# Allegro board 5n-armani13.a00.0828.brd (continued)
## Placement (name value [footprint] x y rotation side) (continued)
PR9413  4.7Ohm  [TX_R0603_H24]  105.82 101.75 90 bottom
PR9414  0Ohm  [TX_R0603_SHORT]  116.92 103.61 0 bottom
PR9415  10KOhm  [TX_R0402]  117.42 95.56 90 bottom
PR9416  4.7KOhm  [TX_R0402]  108.56 96.76 90 bottom
PR9417  2.2Ohm  [TX_R0805_H26]  116.56 97.16 45 bottom
PR9419  845Ohm  [TX_R0402]  110.11 94.6 270 bottom
PR9420  845Ohm  [TX_R0402]  107.19 92.53 90 bottom
PR9421  0Ohm  [TX_R0402_0OHM]  115.86 107.42 270 bottom
PR9422  887Ohm  [TX_R0402]  108.13 92.53 270 bottom
PR9423  10KOhm  [TX_R0402]  112.73 106.07 270 bottom
PR9424  845Ohm  [TX_R0402]  110.01 92.53 90 bottom
PR9425  1Ohm  [TX_R0402]  107.29 94.54 270 bottom
PR9426  0Ohm  [TX_R0402_0OHM]  115.86 105.77 90 bottom
PR9427  10KOhm  [TX_R0402]  114.92 105.77 270 bottom
PR9428  1Ohm  [TX_R0402]  106.35 94.54 270 bottom
PR9429  845Ohm  [TX_R0402]  111.89 92.53 270 bottom
PR9430  10OHM  [TX_R0402]  113.77 92.53 270 bottom
PR9431  887Ohm  [TX_R0402]  110.95 92.53 270 bottom
PR9432  0Ohm  [TX_R0402_0OHM]  114.5 94.16 90 bottom
PR9433  10KOhm  [TX_R0402]  112.66 94.82 270 bottom
PR9434  0Ohm  [TX_R0402_0OHM]  102.34 98.17 0 bottom
PR9435  41.2KOHM  [TX_R0402]  107.87 98.75 0 bottom
PR9436  10OHM  [TX_R0402]  116.36 94.64 270 bottom
PR9437  0Ohm  [TX_R0402_0OHM]  103.96 98.17 0 bottom
PR9438  14.3KOhm  [TX_R0402]  105.74 98.17 180 bottom
PR9439  0Ohm  [TX_R0402_0OHM]  102.34 97.23 0 bottom
PR9440  69.8KOHM  [TX_R0402]  103.96 97.23 0 bottom
PR9441  2.61KOhm  [TX_R0402]  105.74 97.23 0 bottom
PR9442  61.9KOHM  [TX_R0402]  107.28 97.13 270 bottom
PR9443  1.27KOHM  [TX_R0402]  102.34 96.29 0 bottom
PR9444  31.6KOhm  [TX_R0402]  103.96 96.29 0 bottom
PR9445  16.5KOhm  [TX_R0402]  104.65 99.33 0 bottom
PR9446  9.76KOHM  [TX_R0402]  105.93 99.8 270 bottom
PR9447  590OHM  [TX_R0402]  107.95 99.68 0 bottom
PR9448  3.9Ohm  [TX_R0402]  104.14 101.86 180 bottom
PR9449  0Ohm  [TX_R0402_0OHM]  145.62 83.01 0 bottom
PR9450  0Ohm  [TX_R0402_0OHM]  110.41 106.07 90 bottom
PR9451  0Ohm  [TX_R0402_0OHM]  145.62 80.2 0 bottom
PR9452  0Ohm  [TX_R0402_0OHM]  114.71 92.53 270 bottom
PR9453  0Ohm  [TX_R0402_0OHM]  116.59 92.53 90 bottom
PR9454  60.4KOhm  [TX_R0402]  115.42 94.16 270 bottom
PR9455  0Ohm  [TX_R0402_0OHM]  111.73 94.29 90 bottom
PR9456  0Ohm  [TX_R0402_SHORT]  115.65 108.69 0 bottom
PR9457  12KOhm  [R0402_H14]  107.85 102.64 0 bottom
PR9458  10KOhm  [TX_R0402]  143.97 83.01 180 bottom
PR9459  10KOhm  [TX_R0402]  145.62 81.13 180 bottom
PR9460  10KOhm  [TX_R0402]  145.62 79.25 0 bottom
PR9500  100KOhm  [TX_R0402]  163.88 63.93 45 top
PR9501  2.2Ohm  [TX_R0805_H26]  166.4 69.62 90 bottom
PR9502  10KOhm  [TX_R0402]  167.69 67.08 0 bottom
PR9503  10KOhm  [TX_R0402]  163.2 64.59 45 top
PR9504  20KOhm  [TX_R0402]  167.69 66.14 0 bottom
PR9505  100KOhm  [TX_R0402]  165.07 109.6 90 top
PR9506  2.2Ohm  [TX_R0805_H26]  173.58 113.39 180 top
PR9507  10KOhm  [TX_R0402]  165.51 113.18 270 bottom
PR9508  10KOhm  [TX_R0402]  170.28 111.41 270 top
PR9509  5.9KOHM  [TX_R0402]  167.39 113.18 270 bottom
PR9600  0Ohm  [VX_R0805_SMALL_SHORT]  122.31 101.07 180 bottom
PR9601  0Ohm  [VX_R0805_SMALL_SHORT]  122.31 102.8 180 bottom
PR9602  0Ohm  [VX_R0805_SMALL_SHORT]  122.31 104.52 180 bottom
PR9603  0Ohm  [TX_R0805_0OHM_H26]  130.77 96.65 180 bottom
PR9604  8.2KOhm  [TX_R0402]  128.8 95.18 180 bottom
PR9605  0Ohm  [TX_R0805_0OHM_H26]  133.1 96.12 90 bottom
PR9606  4.7OHM  [TX_R1206_H30]  135.1 101.37 180 top
PR9607  0Ohm  [TX_R0805_0OHM_H26]  118.95 105.01 90 bottom
PR9608  8.2KOhm  [TX_R0402]  119.46 107.34 90 bottom
PR9609  0Ohm  [TX_R0805_0OHM_H26]  127.66 104.93 180 bottom
PR9610  4.7OHM  [TX_R1206_H30]  127.61 108.36 180 top
PR9800  0Ohm  [TX_R0603_SHORT]  198.53 66.96 90 bottom
PR9801  0Ohm  [TX_R0402_0OHM]  191.74 67.72 0 top
PR9802  100KOhm  [TX_R0402]  195.61 64.04 270 bottom
PR9803  100KOhm  [TX_R0402]  192.56 64.01 270 bottom
PR9804  100KOhm  [TX_R0402]  191.29 64.01 270 bottom
PR9805  150KOhm  [TX_R0402]  191.74 65.69 180 top
PR9806  100KOhm  [TX_R0402]  194.59 64.04 90 bottom
PR9807  100KOhm  [TX_R0402]  193.57 64.01 90 bottom
PR9808  100KOhm  [TX_R0402]  190.27 64.04 90 bottom
PR9809  5.1OHM  [TX_R0402]  192.43 70.26 270 top
PR9810  2.21KOhm  [TX_R0402]  192.58 70.39 90 bottom
PR9811  6.8OHM  [TX_R0402]  191.57 70.39 270 bottom
PR9812  20KOhm  [TX_R0402]  193.51 70.39 270 bottom
PR9814  10KOhm  [TX_R0402]  192.35 63.71 90 top
PR9815  0Ohm  [TX_R0402_SHORT]  193.29 63.71 270 top
PRT7800  10KOhm  [TX_R0402_H22]  143.41 57.1 0 bottom
PRT7801  10KOhm  [TX_R0402_H22]  143.87 66.22 180 bottom
PRT7802  10KOhm  [TX_R0402_H22]  143.99 32.82 270 bottom
PRT9400  100KOHM  [TX_R0402_H24]  140.11 97.44 0 bottom
PRT9401  100KOHM  [TX_R0402_H24]  138.42 97.44 180 bottom
PT7700  TPC26T_50  [NB_TPC26T_50]  202.62 22.63 180 bottom
PT7701  TPC26T_50  [NB_TPC26T_50]  197.16 27.74 0 top
PT7702  TPC26T_50  [NB_TPC26T_50]  198.87 27.31 180 bottom
PT8700  TPC28T  [NB_TPC28T_68]  171.86 38.81 0 top
PT8701  TPC28T  [NB_TPC28T_68]  165.71 50.04 180 bottom
PT8702  TPC28T  [NB_TPC28T_68]  167.01 57.23 180 bottom
PT8703  TPC28T  [NB_TPC28T_68]  164.44 56.11 180 bottom
PT8704  TPC28T  [NB_TPC28T_68]  173.33 40.9 0 top
PT9400  TPC28T  [NB_TPC28T_68]  109.02 104.56 180 bottom
PT9401  TPC28T  [NB_TPC28T_68]  110.77 104.65 180 bottom
PT9402  TPC28T  [NB_TPC28T_68]  105.92 105.34 180 bottom
PT9403  TPC28T  [NB_TPC28T_68]  109.53 97.18 180 bottom
PT9500  TPC28T  [NB_TPC28T_68]  165.05 63.6 0 top
PT9501  TPC28T  [NB_TPC28T_68]  160.63 65.81 0 top
PT9502  TPC28T  [NB_TPC28T_68]  158.55 66.93 0 top
PT9503  TPC28T  [NB_TPC28T_68]  159.99 68 0 top
PT9504  TPC28T  [NB_TPC28T_68]  157.15 65.89 0 top
PT9505  TPC28T  [NB_TPC28T_68]  152.07 58.47 0 top
PT9506  TPC28T  [NB_TPC28T_68]  163.09 60.86 180 bottom
PT9507  TPC28T  [NB_TPC28T_68]  175.26 66.75 180 bottom
PT9508  TPC28T  [NB_TPC28T_68]  166.78 109.76 0 top
PT9509  TPC28T  [NB_TPC28T_68]  172.77 108.74 180 bottom
PT9510  TPC28T  [NB_TPC28T_68]  165.13 111.15 180 bottom
PT9511  TPC28T  [NB_TPC28T_68]  170.15 106.3 180 bottom
PT9512  TPC28T  [NB_TPC28T_68]  168.43 106.3 180 bottom
PT9513  TPC28T  [NB_TPC28T_68]  152.27 66.83 0 top
PT9514  TPC28T  [NB_TPC28T_68]  152.25 65.03 0 top
PT9515  TPC28T  [NB_TPC28T_68]  174.78 109.88 180 bottom
PT9800  TPC28T  [NB_TPC28T_68]  195.33 68.28 0 top
PU7600  R3118K161A-TR  [TX_DFN_6P_16_51X51]  36.42 87.2 180 top
PU7700  ISL9538HRTZ-T  [TX_QFN_32P_16_S161_PAD_5V]  195.99 25.69 180 bottom
PU7800  ISL95859AHRTZ  [A_QFN_40P_16_201X201_PAD_8V]  174.9 49.05 0 bottom
PU7900  ISL95808HRZ  [TX_DFN_8P_20_87X87_PAD_1V]  160.2 45.11 0 bottom
PU7901  ISL95808HRZ  [TX_DFN_8P_20_87X87_PAD_1V]  160.15 54.38 0 bottom
PU8000  ISL95808HRZ  [TX_DFN_8P_20_87X87_PAD_1V]  146.25 29.57 270 bottom
PU8001  ISL95808HRZ  [TX_DFN_8P_20_87X87_PAD_1V]  160.91 64.67 0 bottom
PU8600  RT8231BGQW  [TX_QFN_20P_16_S118_P_H31_4V]  100.48 97.82 0 top
PU8700  NB685AGQ-Z  [QFN_16P_20_118X118_MPS]  175.13 36.32 270 bottom
PU8800  RT8068AZQW  [TX_DFN_10P_20_S122_P_4V]  44.88 15.65 270 bottom
PU8801  RT8068AZQW  [TX_DFN_10P_20_S122_P_4V]  108.64 111.81 90 bottom
PU8900  RT6575DGQW  [A_QFN_20P_16_S122_P_4V]  200.3 59.21 180 bottom
PU9000  TC7SZ08FU  [TX_SC70_S5_TI]  46.99 72.32 90 top
PU9001  APL3523AQB-ITRG  [TX_DFN_10P_16_122X83_P_COLA]  35.84 70.13 90 top
PU9100  APL3523AQB-ITRG  [TX_DFN_10P_16_122X83_P_COLA]  199.52 51.58 90 bottom
PU9101  APL3523AQB-ITRG  [TX_DFN_10P_16_122X83_P_COLA]  179.71 14.35 180 bottom
PU9200  APL3523AQB-ITRG  [TX_DFN_10P_16_122X83_P_COLA]  138.56 23.78 270 bottom
PU9400  RT3662ACGQW  [TX_QFN_40P_16_S201_P_4V_H31]  112.67 100.61 180 bottom
PU9500  SY8003DFC  [TX_DFN_8P_20_S83_PAD_1V]  164.11 66.7 180 bottom
PU9501  RT8068AZQW  [TX_DFN_10P_20_S122_P_4V]  170.46 111.79 180 bottom
PU9800  NB681AGD-Z  [TX_QFN_13P_122X83]  192.18 67.08 270 bottom
Q0400  NX7002AK  [TX_SOT23_2D4_H44]  136.8 76.81 180 bottom
Q1000  NX7002AK  [TX_SOT23_2D4_H44]  109.37 19.36 0 bottom
Q1900  UM6K1N  [TX_SC70_S6_H47]  18.9 46.28 0 bottom
Q1901  UM6K1N  [TX_SC70_S6_H47]  78.18 17 270 bottom
Q1902  UM6K1N  [TX_SC70_S6_H47]  78.23 14.76 270 bottom
Q2400  UM6K1N  [TX_SC70_S6_H47]  19.71 52.07 180 top
Q2401  UM6K1N  [TX_SC70_S6_H47]  27.2 21.24 270 top
Q2403  NX7002AK  [TX_SOT23_2D4_H44]  101.18 16.31 90 bottom
Q2406  PJA3411  [TX_SOT23_2D4_122X55_H43]  102.15 12.97 270 bottom
Q2600  PJA3411  [TX_SOT23_2D4_122X55_H43]  23.01 70.41 180 top
Q2601  NX7002AK  [TX_SOT23_2D4_H44]  26.64 71.07 180 top
Q2900  UM6K1N  [TX_SC70_S6_H47]  26.64 65.71 0 top
Q2901  UM6K1N  [TX_SC70_S6_H47]  29.44 67.85 0 top
Q3100  NX7002AK  [TX_SOT23_2D4_H44]  159.84 12.35 180 bottom
Q3101  UM6K1N  [TX_SC70_S6_H47]  155.42 16.66 90 bottom
Q3102  NX7002AK  [TX_SOT23_2D4_H44]  156.67 12.35 180 bottom
Q3600  NX7002AK  [TX_SOT23_2D4_H44]  147.77 17.25 0 bottom
Q3601  NX7002AK  [TX_SOT23_2D4_H44]  109.93 78.67 90 bottom
Q3602  NX7002AK  [TX_SOT23_2D4_H44]  205.83 89.18 90 bottom
Q3700  PMBS3904  [TX_SOT23_2D4_H43]  204.11 108.08 270 bottom
Q3701  UM6K1N  [TX_SC70_S6_H47]  121.46 18.04 270 bottom
Q5000  UM6K1N  [TX_SC70_S6_H47]  19.76 85.42 90 bottom
Q5002  UM6K1N  [TX_SC70_S6_H47]  16.74 85.82 0 bottom
Q5100  NX7002AK  [TX_SOT23_2D4_H44]  163.13 16.47 180 bottom
Q5101  PJA3411  [TX_SOT23_2D4_122X55_H43]  44.63 11.43 270 bottom
Q5102  UM6K1N  [TX_SC70_S6_H47]  45.24 5.11 180 bottom
Q5103  UM6K1N  [TX_SC70_S6_H47]  44.27 8.28 90 bottom
Q5104  UM6K1N  [TX_SC70_S6_H47]  42.95 5.11 180 bottom
Q5800  NX7002AK  [TX_SOT23_2D4_H44]  15.16 72.24 0 bottom
Q5801  NX7002AK  [TX_SOT23_2D4_H44]  116.61 17.78 90 bottom
Q6900  UM6K1N  [TX_SC70_S6_H47]  145.31 84.61 90 bottom
Q6901  NX7002AK  [TX_SOT23_2D4_H44]  146.41 75.36 90 bottom
Q7200  NX7002AK  [TX_SOT23_2D4_H44]  207.06 113.06 270 bottom
Q7201  NX7002AK  [TX_SOT23_2D4_H44]  203.1 113.06 270 bottom
Q7202  NX7002AK  [TX_SOT23_2D4_H44]  207.78 108.32 180 bottom
Q7203  NX7002AK  [TX_SOT23_2D4_H44]  158.35 107.12 270 bottom
Q7204  NX7002AK  [TX_SOT23_2D4_H44]  207.8 104.37 180 bottom
R0400  1KOhm  [TX_R0402]  137.03 65.86 90 bottom
R0401  51Ohm  [TX_R0402]  129.64 76.94 90 top
R0402  51Ohm  [TX_R0402]  130.56 76.94 90 top
R0403  100Ohm  [TX_R0402]  133.33 61.85 0 bottom
R0404  49.9Ohm  [TX_R0402]  109.12 43.41 270 top
R0405  49.9Ohm  [TX_R0402]  105.84 43.61 270 top
R0406  49.9Ohm  [TX_R0402]  128.09 76.94 270 top
R0407  49.9Ohm  [TX_R0402]  122.6 65.78 180 top
R0408  0Ohm  [TX_R0402_SHORT]  126.12 29.26 270 top
R0410  499Ohm  [TX_R0402]  134.96 67.39 180 bottom
R0411  100KOhm  [TX_R0402]  126.16 25.5 0 top
R0413  24.9Ohm  [TX_R0402]  125.51 61.88 270 top
R0414  2.2kOHM  [TX_R0402]  126.21 27.36 90 top
R0415  100KOhm  [TX_R0402]  127.15 29.09 90 top
R0416  100Ohm  [TX_R0402]  134.11 76.81 270 bottom
R0417  1KOhm  [TX_R0402]  132.91 63.71 180 bottom
R0418  160KOhm  [TX_R0402_H16]  133.78 74.58 0 bottom
R0420  51Ohm  [TX_R0402]  132.91 62.79 180 bottom
R0500  121OHM  [TX_R0402]  110.06 42.95 90 top
R0501  80.6Ohm  [TX_R0402]  108.18 43.41 90 top
R0502  100Ohm  [TX_R0402]  106.83 43.61 90 top
R0503  4.7KOhm  [TX_R0402]  97.03 109.95 270 bottom
R0504  10KOhm  [TX_R0402]  95.25 113.79 90 bottom
R0600  0Ohm  [TX_R0402_0OHM]  107.7 56.71 180 top
R0601  56Ohm  [TX_R0402]  134.94 65.52 0 bottom
R0602  100Ohm  [TX_R0402]  134.94 66.45 0 bottom
R0603  220Ohm  [TX_R0402]  132.91 65.55 0 bottom
R0604  0Ohm  [TX_R0402_0OHM]  132.91 64.63 180 bottom
R0605  0Ohm  [TX_R0402_0OHM]  132.91 66.49 180 bottom
R0606  100Ohm  [TX_R0402]  124.59 52.12 180 top
R0607  100Ohm  [TX_R0402]  125.55 50.7 0 top
R0608  100Ohm  [TX_R0402]  170.82 43 180 bottom
R0609  100Ohm  [TX_R0402]  171.81 44.33 270 bottom
R0700  0ohm  [TX_R0805_0OHM_T02_H20]  119.79 58.32 90 top
R0701  0ohm  [TX_R0805_0OHM_T02_H20]  119.79 61.08 270 top
R0702  100Ohm  [TX_R0402]  179.53 51.34 90 top
R0703  100Ohm  [TX_R0402]  180.95 51.01 180 top
R0900  49.9Ohm  [TX_R0402]  125.59 65.43 270 top
R0901  1KOhm  [TX_R0402]  126.49 77.4 90 bottom
R0902  100KOhm  [TX_R0402]  134.95 64.59 0 bottom
R0903  1MOhm  [TX_R0402]  128.6 27.21 180 bottom
R0904  0Ohm  [TX_R0402_0OHM]  127.61 28.15 180 bottom
R0905  0Ohm  [TX_R0402_0OHM]  129.24 28.3 0 bottom
R1000  1MOhm  [TX_R0402]  132.54 52.91 90 bottom
R1001  0Ohm  [TX_R0402_0OHM]  131.6 53.6 270 bottom
R1002  10KOhm  [TX_R0402]  104.62 30.43 90 top
R1003  10KOhm  [TX_R0402]  106.5 30.43 90 top
R1004  10KOhm  [TX_R0402]  103.68 30.43 90 top
R1005  2.7KOhm  [TX_R0402]  126.97 52.56 180 top
R1006  60.4Ohm  [TX_R0402]  128.67 52.38 270 top
R1007  10MOhm  [TX_R0402]  94.67 43.47 270 top
R1008  0Ohm  [TX_R0402_0OHM]  92.66 42.24 270 top
R1009  20KOhm  [TX_R0402]  110.64 23.29 90 bottom
R1010  10KOhm  [TX_R0402]  105.56 30.43 90 top
R1011  20KOhm  [TX_R0402]  111.58 23.29 90 bottom
R1012  1KOhm  [TX_R0402]  99.01 45.82 180 bottom
R1013  33Ohm  [TX_R0402]  98.32 44.76 180 bottom
R1014  33Ohm  [TX_R0402]  98.32 43.82 180 bottom
R1015  33Ohm  [TX_R0402]  97.31 45.7 180 bottom
R1016  33Ohm  [TX_R0402]  91.31 21.97 180 bottom
R1017  10KOhm  [TX_R0402]  123.67 24.46 0 top
R1018  10KOhm  [TX_R0402]  125.3 24.51 0 top
R1019  100KOhm  [TX_R0402]  107.26 23.68 0 bottom
R1020  0Ohm  [TX_R0402_0OHM]  131.6 51.97 270 bottom
R1021  1KOhm  [TX_R0402]  96.9 30.43 90 bottom
R1022  10KOhm  [TX_R0402]  112.42 26.19 90 top
R1023  10KOhm  [TX_R0402]  112.66 28.48 270 top
R1024  10KOhm  [TX_R0402]  113.34 26.19 90 top
R1025  10KOhm  [TX_R0402]  114.25 26.19 90 top
R1026  10KOhm  [TX_R0402]  115.16 26.19 90 top
R1027  10KOhm  [TX_R0402]  113.59 28.48 270 top
R1028  10KOhm  [TX_R0402]  114.23 31.25 270 top
R1029  10KOhm  [TX_R0402]  114.71 28.53 270 top
R1030  10KOhm  [TX_R0402]  102.74 30.43 270 top
R1100  1KOhm  [TX_R0402]  124.98 28.69 90 top
R1101  1KOhm  [TX_R0402]  123.52 28.88 90 top
R1102  1KOhm  [TX_R0402]  121.13 22.8 90 bottom
R1103  1KOhm  [TX_R0402]  123.01 22.8 90 bottom
R1104  1KOhm  [TX_R0402]  122.83 24.44 90 bottom
R1105  1KOhm  [TX_R0402]  123.77 24.44 90 bottom
R1106  150KOhm  [TX_R0402]  111.49 27.56 90 top
R1107  10KOhm  [TX_R0402]  99.72 32.53 90 bottom
R1108  15Ohm  [TX_R0402]  100.71 32.51 270 bottom
R1109  1KOhm  [TX_R0402]  122.07 22.8 90 bottom
R1110  15Ohm  [TX_R0402]  94.46 37.04 270 top
R1111  15Ohm  [TX_R0402]  93.55 37.04 270 top
R1112  15Ohm  [TX_R0402]  92.61 37.04 270 top
R1113  15Ohm  [TX_R0402]  91.57 37.04 270 top
R1114  1KOhm  [TX_R0402]  122.56 28.35 90 top
R1115  15Ohm  [TX_R0402]  97.84 30.43 270 bottom
R1200  100KOhm  [TX_R0402]  95.22 32.9 90 top
R1201  0Ohm  [TX_R0402_0OHM]  100.76 28.22 90 bottom
R1202  60.4Ohm  [TX_R0402]  129.7 77.37 270 bottom
R1203  10KOhm  [TX_R0402]  97.83 32.51 90 bottom
R1204  10KOhm  [TX_R0402]  92.66 28.35 90 top
R1205  10KOhm  [TX_R0402]  139.34 32.77 180 top
R1206  1MOhm  [TX_R0402]  109.7 23.29 90 bottom
R1207  10KOhm  [TX_R0402]  98.78 32.57 270 bottom
R1208  10KOhm  [TX_R0402]  90.79 28.37 90 top
R1209  10KOhm  [TX_R0402]  91.72 28.37 90 top
R1210  10KOhm  [TX_R0402]  116.08 26.19 90 top
R1211  0Ohm  [TX_R0402_SHORT]  128.19 26.52 90 top
R1212  100KOhm  [TX_R0402]  128.19 24.87 270 top
R1213  10KOhm  [TX_R0402]  97.54 42.62 180 bottom
R1214  1KOhm  [TX_R0402]  96.89 32.48 90 bottom
R1216  0Ohm  [TX_R0402_SHORT]  97.26 40.72 180 bottom
R1217  0Ohm  [TX_R0402_0OHM]  70.56 7.83 270 top
R1218  100KOhm  [TX_R0402]  65.76 13.34 90 top
R1220  10KOhm  [TX_R0402]  63.78 12.98 180 top
R1221  0Ohm  [TX_R0402_0OHM]  62.13 12.98 0 top
R1222  100KOhm  [TX_R0402]  102.51 25.3 90 bottom
R1223  0Ohm  [TX_R0402_SHORT]  102.84 27.99 270 bottom
R1224  1KOhm  [TX_R0402]  98.07 17.05 180 bottom
R1225  47KOhm  [TX_R0402]  101.68 28.22 90 bottom
R1226  10KOhm  [TX_R0402]  90.69 26.75 270 top
R1227  0Ohm  [TX_R0402_0OHM]  97.84 24.59 270 bottom
R1228  0Ohm  [TX_R0402_SHORT]  96.93 24.59 90 bottom
R1229  0Ohm  [TX_R0402_0OHM]  90.6 30.41 90 top
R1300  100Ohm  [TX_R0402]  130.94 40.91 270 bottom
R1301  200Ohm  [TX_R0402]  107.42 28.4 270 bottom
R1400  113Ohm  [TX_R0402]  114.76 26.93 0 bottom
R1401  100Ohm  [TX_R0402]  130.99 32.62 270 bottom
R1402  10KOhm  [TX_R0402]  132.97 41.28 180 bottom
R1403  10KOhm  [TX_R0402]  132.97 42.22 180 bottom
R1404  10KOhm  [TX_R0402]  135.31 42.22 270 bottom
R1405  10KOhm  [TX_R0402]  134.37 42.22 270 bottom
R1406  0Ohm  [TX_R0402_SHORT]  129.46 22.15 0 bottom
R1407  0Ohm  [TX_R0402_SHORT]  123.91 28.46 270 bottom
R1408  0Ohm  [TX_R0402_SHORT]  124.83 28.46 270 bottom
R1409  10KOhm  [TX_R0402]  125.85 28.5 90 bottom
R1410  1KOhm  [TX_R0402]  111.99 28.53 270 bottom
R1411  1KOhm  [TX_R0402]  112.93 28.63 270 bottom
R1500  1KOhm  [TX_R0402]  101.6 30.43 90 bottom
R1503  10KOhm  [TX_R0402]  118.85 22.86 270 top
R1504  10KOhm  [TX_R0402]  124.71 24.44 90 bottom
R1505  10KOhm  [TX_R0402]  125.65 24.77 270 bottom
R1506  10KOhm  [TX_R0402]  115.7 28.53 90 bottom
R1507  10KOhm  [TX_R0402]  110.57 27.56 90 top
R1508  10KOhm  [TX_R0402]  110.61 29.38 270 top
R1509  10KOhm  [TX_R0402]  117.86 23.52 0 bottom
R1510  10KOhm  [TX_R0402]  120.19 22.8 90 bottom
R1511  10KOhm  [TX_R0402]  118.14 25.43 180 bottom
R1512  10KOhm  [TX_R0402]  119.25 22.8 270 bottom
R1513  49.9KOhm  [TX_R0402]  113.87 28.53 90 bottom
R1514  49.9KOhm  [TX_R0402]  114.78 28.53 90 bottom
R1515  1KOhm  [TX_R0402]  113.28 21.41 90 bottom
R1516  2.7KOhm  [TX_R0402]  112.34 21.41 90 bottom
R1517  10KOhm  [TX_R0402]  92.86 32.36 180 top
R1518  10KOhm  [TX_R0402]  95.99 12.65 0 bottom
R1519  10KOhm  [TX_R0402]  118.72 26.53 270 top
R1520  100KOhm  [TX_R0402]  148.97 21.21 270 bottom
R1600  0Ohm  [TX_R0603_SHORT]  134.65 27.81 90 bottom
R1601  0Ohm  [TX_R0402_SHORT]  134.8 31.04 180 bottom
R1602  0Ohm  [TX_R0402_SHORT]  134.65 32.95 180 bottom
R1604  0Ohm  [TX_R0402_SHORT]  120.17 26.8 90 top
R1606  0Ohm  [TX_R0402_SHORT]  126.04 42.32 0 top
R1607  1KOhm  [TX_R0402]  117.01 25.17 270 top
R1608  1KOhm  [TX_R0402]  112.23 31.44 270 top
R1609  0Ohm  [TX_R0603_SHORT]  132.82 31.09 180 bottom
R1610  0Ohm  [TX_R0402_SHORT]  126.01 46.46 0 top
R1611  0Ohm  [TX_R0402_SHORT]  127.03 44.2 270 top
R1612  0Ohm  [TX_R0402_SHORT]  129.24 26.52 90 top
R1613  0Ohm  [TX_R0603_SHORT]  138.15 29.42 90 bottom
R1614  0Ohm  [TX_R0402_SHORT]  112.47 18.39 90 bottom
R1615  0Ohm  [TX_R0402_0OHM]  121.64 28.35 270 top
R1620  0Ohm  [TX_R0603_SHORT]  133.43 27.81 90 bottom
R1621  0Ohm  [TX_R0402_SHORT]  133.5 27.05 90 top
R1622  0Ohm  [TX_R0402_SHORT]  113.67 42.67 270 top
R1623  0Ohm  [TX_R0402_SHORT]  109.32 23.85 270 top
R1624  0Ohm  [TX_R0402_SHORT]  120.37 29.01 0 top
R1625  0Ohm  [TX_R0603_SHORT]  133.22 31.55 180 top
R1800  0Ohm  [TX_R0402_SHORT]  65.35 7.95 90 top
R1801  0Ohm  [TX_R0402_SHORT]  64.41 7.95 90 top
R1802  10KOhm  [TX_R0402]  66.83 7.95 90 top
R1803  0Ohm  [TX_R0402_SHORT]  68.5 8.05 90 top
R1804  10KOhm  [TX_R0402]  70.56 10.82 270 top
R1805  0Ohm  [TX_R0402_SHORT]  69.44 8.05 270 top
R1806  0Ohm  [TX_R0402_0OHM]  69.24 10.47 180 top
R1807  100KOhm  [TX_R0402]  69.57 13.34 180 top
R1900  33Ohm  [TX_R0402]  104.57 23.47 270 bottom
R1901  0Ohm  [TX_R0402_SHORT]  105.54 19.64 270 bottom
R1902  10KOhm  [TX_R0402]  93.88 18.44 90 bottom
R1903  10KOhm  [TX_R0402]  93.88 22 270 bottom
R1904  10KOhm  [TX_R0402]  104.62 19.64 90 bottom
R1905  33Ohm  [TX_R0402]  93.88 20.35 270 bottom
R1906  33Ohm  [TX_R0402]  104.61 21.29 270 bottom
R1907  0Ohm  [TX_R0402_SHORT]  80.61 16.51 270 bottom
R1908  0Ohm  [TX_R0402_SHORT]  91.64 13.68 180 bottom
R1909  0Ohm  [TX_R0402_SHORT]  19.69 49.2 270 bottom
R1910  0Ohm  [TX_R0402_SHORT]  17.91 43.4 90 bottom
R1911  10KOhm  [TX_R0402]  17.09 49.1 270 bottom
R1912  10KOhm  [TX_R0402]  20.73 45.37 270 bottom
R1913  10KOhm  [TX_R0402]  18.85 43.4 90 bottom
R1914  0Ohm  [TX_R0402_SHORT]  74.83 16.97 270 top
R1915  10KOhm  [TX_R0402]  76.68 17.73 270 top
R1916  0Ohm  [TX_R0402_SHORT]  44.6 21.8 90 top
R1917  4.7KOhm  [TX_R0402]  75.77 17.73 270 top
R1918  4.7KOhm  [TX_R0402]  75.13 21.03 90 top
R1919  1KOhm  [TX_R0402]  74.45 15.55 180 top
R1920  10KOhm  [TX_R0402]  88.01 9.98 180 top
R1921  1KOhm  [TX_R0402]  77.39 14.12 0 top
R2000  470Ohm  [TX_R0402]  62.1 62.84 0 top
R2001  0 Ohm  [TX_R0402_0OHM]  62.1 63.78 180 top
R2002  240Ohm  [TX_R0402]  65.96 58.8 180 top
R2003  1KOhm  [TX_R0402]  61.54 46.73 0 top
R2004  2Ohm  [TX_R0402]  61.54 48.61 0 top
R2005  1KOhm  [TX_R0402]  61.54 49.57 180 top
R2006  24.9Ohm  [TX_R0402]  59.39 48.3 0 top
R2100  240Ohm  [TX_R0402]  49.96 55.93 180 top
R2101  1KOhm  [TX_R0402]  49.61 50.7 0 top
R2102  2Ohm  [TX_R0402]  49.61 49.76 0 top
R2103  1KOhm  [TX_R0402]  49.6 48.84 180 top
R2104  24.9Ohm  [TX_R0402]  47.56 52.47 0 top
R2300  43Ohm  [TX_R0402]  40.03 25.73 270 top
R2301  0Ohm  [TX_R0402_SHORT]  48.16 37.77 270 top
R2302  0Ohm  [TX_R0402_SHORT]  45.03 39.12 0 top
R2305  330Ohm  [TX_R0402]  47.88 36.02 0 top
R2306  1KOhm  [TX_R0402]  46.79 39.7 270 top
R2307  0Ohm  [TX_R0402_SHORT]  45.06 47.6 90 top
R2308  0Ohm  [TX_R0402_SHORT]  44.96 40.96 180 top
R2309  1KOhm  [TX_R0402]  46.82 55.3 90 top
R2310  100KOhm  [TX_R0402]  46.81 57.18 270 top
R2311  330Ohm  [TX_R0402]  46.19 33.1 0 top
R2312  27KOhm  [TX_R0402]  45.69 31.49 270 top
R2313  100KOhm  [TX_R0402]  46.61 31.49 270 top
R2314  49.9KOhm  [TX_R0402]  46.81 34.37 270 top
R2315  100KOhm  [TX_R0402]  45.9 34.37 90 top
R2316  100Ohm  [TX_R0402]  38.51 47.14 270 top
R2317  100Ohm  [TX_R0402]  37.47 46.66 270 top
R2318  4.7KOhm  [TX_R0402]  37.95 52.2 90 top
R2319  4.7KOhm  [TX_R0402]  38.73 49.57 270 top
R2320  100KOhm  [TX_R0402]  29.82 25.5 90 top
R2321  0Ohm  [TX_R0402_SHORT]  41.91 25.73 270 top
R2322  100KOhm  [TX_R0402]  30.23 49.18 90 top
R2323  0Ohm  [TX_R0402_SHORT]  30.12 47.07 270 top
R2324  10KOhm  [TX_R0402]  46.89 37.43 0 top
R2325  10KOhm  [TX_R0402]  46.89 38.36 180 top
R2326  100KOhm  [TX_R0402]  36.2 46.71 0 top
R2328  0Ohm  [TX_R0402_0OHM]  45.11 35.66 180 top
R2329  0Ohm  [TX_R0402_0OHM]  45.36 42.88 0 top
R2330  0Ohm  [TX_R0402_0OHM]  45.42 43.92 0 top
R2331  10KOhm  [TX_R0402]  24.12 34.48 0 top
R2332  100KOhm  [TX_R0402]  44.98 40.03 0 top
R2333  100KOhm  [TX_R0402]  37.31 24.95 90 top
R2334  100KOhm  [TX_R0402]  24.1 44.2 0 top
R2335  100KOhm  [TX_R0402]  24.16 36.79 0 top
R2336  0Ohm  [TX_R0402_SHORT]  24.13 35.41 180 top
R2337  4.7KOhm  [TX_R0402]  35.13 23.37 90 top
R2338  4.7KOhm  [TX_R0402]  34.19 23.37 90 top
R2339  100KOhm  [TX_R0402]  44.4 54.94 270 top
R2341  10KOhm  [TX_R0402]  40.44 47.17 270 top
R2342  100KOhm  [TX_R0402]  43.5 47.8 180 top
R2343  100KOhm  [TX_R0402]  44.73 31.52 90 top
R2344  100KOhm  [TX_R0402]  28.6 25.55 270 top
R2345  0Ohm  [TX_R0402_SHORT]  24.08 41.63 180 top
R2346  0Ohm  [TX_R0402_SHORT]  29.08 46.97 270 top
R2347  100KOhm  [TX_R0402]  24.08 38.03 0 top
R2348  100KOhm  [TX_R0402]  43.35 54.93 270 top
R2349  100KOhm  [TX_R0402]  32.18 25.61 90 top
R2351  82.5KOhm  [TX_R0402]  46.91 28.86 180 top
R2400  0Ohm  [TX_R0402_SHORT]  36.37 24.97 270 top
R2401  0Ohm  [TX_R0402_SHORT]  17.91 49.18 270 top
R2402  0Ohm  [TX_R0402_SHORT]  17.93 50.93 270 top
R2403  0Ohm  [TX_R0402_SHORT]  13.39 19.26 90 top
R2404  0Ohm  [TX_R0402_0OHM]  17.53 54.97 180 top
R2405  1MOhm  [TX_R0402]  17.93 52.73 90 top
R2406  1MOhm  [TX_R0402]  21.95 51.41 180 top
R2407  3.3KOhm  [TX_R0402]  22.1 52.45 180 top
R2408  1MOhm  [TX_R0402]  21.95 50.37 0 top
R2409  0Ohm  [TX_R0402_SHORT]  27.36 24.34 180 top
R2410  0Ohm  [TX_R0402_SHORT]  27.99 23.29 180 top
R2411  10KOhm  [TX_R0402]  25.73 24.34 0 top
R2412  20KOhm  [TX_R0402]  32.31 49.18 270 top
R2413  10KOhm  [TX_R0402]  31.27 49.18 90 top
R2414  20KOhm  [TX_R0402]  30.53 20.37 0 top
R2415  20KOhm  [TX_R0402]  103.76 15.45 270 bottom
R2416  49.9KOhm  [TX_R0402]  100.15 14.3 180 bottom
R2423  100KOhm  [TX_R0402]  30.94 25.5 270 top
R2424  100KOhm  [TX_R0402]  12.47 19.26 90 top
R2425  0Ohm  [TX_R0402_0OHM]  104.7 15.45 90 bottom
R2428  0Ohm  [TX_R0402_0OHM]  99.39 12.6 180 bottom
R2500  0Ohm  [TX_R0402_0OHM]  94.08 21.89 90 top
R2501  20KOhm  [TX_R0402]  96.32 30.45 270 top
R2502  20KOhm  [TX_R0402]  98.17 30.45 270 top
R2503  20KOhm  [TX_R0402]  100.1 30.45 270 top
R2504  20KOhm  [TX_R0402]  94.46 30.45 270 top
R2505  20KOhm  [TX_R0402]  95.39 30.45 270 top
R2506  20KOhm  [TX_R0402]  97.24 30.45 270 top
R2507  20KOhm  [TX_R0402]  99.16 30.45 270 top
R2508  20KOhm  [TX_R0402]  101.04 30.45 270 top
R2509  20KOhm  [TX_R0402]  92.23 22.07 270 top
R2510  0Ohm  [TX_R0402_SHORT]  90.27 24.4 270 top
R2511  0Ohm  [TX_R0402_SHORT]  94.11 26.04 270 top
R2512  20KOhm  [TX_R0402]  93.17 22.07 90 top
R2513  20KOhm  [TX_R0402]  90.35 22.63 90 top
R2514  10KOhm  [TX_R0402]  91.29 22.12 270 top
R2600  10KOhm  [TX_R0402]  28.78 72.32 90 top
R2601  100KOhm  [TX_R0402]  22.02 73 0 top
R2602  20KOhm  [TX_R0402]  14.28 77.04 270 top
R2607  220Ohm  [TX_R0402]  18.85 64.65 270 bottom
R2608  220Ohm  [TX_R0402]  19.58 62.51 270 bottom
R2609  220Ohm  [TX_R0402]  19.58 59.97 270 bottom
R2610  220Ohm  [TX_R0402]  19.58 67.06 270 bottom
R2900  2.2kOHM  [TX_R0402]  26.01 63.32 180 top
R2901  2.2kOHM  [TX_R0402]  28.55 65 90 top
R2903  470Ohm  [TX_R0402]  21.16 65.2 180 top
R2904  470Ohm  [TX_R0402]  21.16 64.28 180 top
R2905  470Ohm  [TX_R0402]  21.97 62.87 180 top
R2906  470Ohm  [TX_R0402]  21.97 61.95 180 top
R2907  470Ohm  [TX_R0402]  21.97 60.43 180 top
R2908  470Ohm  [TX_R0402]  21.97 59.51 180 top
R2909  470Ohm  [TX_R0402]  22.02 67.52 180 top
R2910  470Ohm  [TX_R0402]  22.02 66.6 180 top
R2911  2.2kOHM  [TX_R0402]  15.14 67.34 180 top
R2912  2.2kOHM  [TX_R0402]  15.11 68.48 180 top
R2913  1MOhm  [TX_R0402]  29.67 70.36 180 top
R3000  0Ohm  [TX_R0402_SHORT]  63.83 98.16 90 bottom
R3001  0Ohm  [TX_R0402_SHORT]  62.92 98.26 90 bottom
R3002  0Ohm  [TX_R0402_0OHM]  61.37 96.95 180 bottom
R3003  150Ohm  [TX_R0402]  50.47 99.65 0 bottom
R3004  0Ohm  [TX_R0402_SHORT]  56.64 99.05 0 top
R3005  100KOhm  [TX_R0402]  79.93 99.06 270 bottom
R3006  0Ohm  [TX_R0603_SHORT]  63.12 100.48 0 top
R3007  0Ohm  [TX_R0603_SHORT]  63.12 99.09 0 top
R3008  0Ohm  [TX_R0603_SHORT]  59.51 101.5 180 top
R3009  10KOhm  [TX_R0402]  56.36 96.62 180 top
R3102  0Ohm  [TX_R0402_0OHM]  219.33 16.11 180 top
R3103  0Ohm  [TX_R0402_SHORT]  219.86 6.56 0 top
R3104  0Ohm  [TX_R0402_SHORT]  221.79 5.79 0 top
R3105  10KOhm  [TX_R0402]  217.96 4.45 180 top
R3106  0Ohm  [TX_R0402_0OHM]  216.54 3.99 90 top
R3107  10KOhm  [TX_R0402]  217.96 2.61 0 top
R3108  0Ohm  [TX_R0805_0OHM_H26]  106.71 14.94 0 bottom
R3109  10KOhm  [TX_R0402]  156.36 18.24 0 bottom
R3110  10KOhm  [TX_R0402]  154.71 18.24 180 bottom
R3111  0Ohm  [TX_R0402_0OHM]  213.74 10.67 180 bottom
R3112  0Ohm  [TX_R0402_0OHM]  213.72 9.75 180 bottom
R3113  10KOhm  [TX_R0402]  221.82 4.85 0 top
R3114  10KOhm  [TX_R0402]  217.96 3.53 180 top
R3115  0Ohm  [TX_R0402_0OHM]  153.04 16.97 90 bottom
R3116  0Ohm  [TX_R0402_0OHM]  221.39 16.97 270 top
R3600  0Ohm  [TX_R0603_SHORT]  206.65 85.83 180 bottom
R3601  8.2KOhm  [TX_R0402]  203.23 91.04 90 bottom
R3602  4.7KOhm  [TX_R0402]  206.4 86.9 0 bottom
R3606  100KOhm  [TX_R0402]  143.71 18.82 0 bottom
R3607  200Ohm  [TX_R0402]  138.42 18.63 270 bottom
R3608  10KOhm  [TX_R0402]  142.06 17.88 180 bottom
R3609  10MOhm  [TX_R0402]  61.8 23.68 90 top
R3610  0Ohm  [TX_R0402_0OHM]  204.65 91.47 180 bottom
R3611  10KOhm  [TX_R0402]  208.86 87.53 0 bottom
R3612  1KOhm  [TX_R0402]  60.5 22.99 180 top
R3613  1.5KOHM  [TX_R0402]  99.06 86.18 0 top
R3614  45.3KOHM  [TX_R0402]  98.4 81.05 270 top
R3700  100KOhm  [TX_R0402]  150.72 22 0 top
R3701  100KOhm  [TX_R0402]  150.72 21.06 0 top
R3702  0Ohm  [TX_R0402_SHORT]  154.51 25.86 0 top
R3703  100KOhm  [TX_R0402]  150.72 20.12 180 top
R3704  0Ohm  [TX_R0402_SHORT]  153.24 24.77 270 top
R3705  0Ohm  [TX_R0402_SHORT]  150.72 24.31 0 top
R3706  0Ohm  [TX_R0402_SHORT]  154.51 27.13 0 top
R3707  100KOhm  [TX_R0402]  8.53 56.34 180 top
R3708  7.5KOHM  [TX_R0402]  128.75 93.91 90 bottom
R3709  12.1KOhm  [TX_R0402]  94.18 45.77 90 top
R3710  1KOhm  [TX_R0402]  124.16 18.16 180 bottom
R3711  1KOhm  [TX_R0402]  124.35 22.41 90 bottom
R3712  1KOhm  [TX_R0402]  124.13 16.69 180 bottom
R3713  1KOhm  [TX_R0402]  125.58 22.42 90 bottom
R3714  10KOhm  [TX_R0402]  119.1 16.61 90 bottom
R3715  10.5KOHM  [TX_R0402]  131.19 87.58 0 bottom
R3800  2.2kOHM  [TX_R0402]  8.99 53.39 180 bottom
R3801  2.2kOHM  [TX_R0402]  13.91 28.51 90 top
R3802  13.7Ohm  [TX_R0603_H22]  14.15 45.62 90 bottom
R3803  13.7Ohm  [TX_R0603_H22]  7.7 40.13 90 bottom
R3804  0Ohm  [TX_R0402_0OHM]  15.55 35.89 180 top
R3805  22Ohm  [TX_R0402]  21.16 24.82 180 bottom
R3806  0Ohm  [TX_R0603_0OHM_H24]  4.8 15.84 270 top
R3807  0Ohm  [TX_R0603_0OHM_H24]  6.17 15.84 270 top
R3808  22Ohm  [TX_R0402]  21.95 28.26 180 bottom
R3809  100KOhm  [TX_R0402]  21.81 35.17 180 bottom
R3810  200KOhm  [TX_R0402]  15.69 38.47 0 bottom
R3811  10KOhm  [TX_R0402]  21.82 32.33 180 bottom
R3812  0Ohm  [TX_R0603_0OHM_H24]  7.49 15.81 270 top
R3813  0Ohm  [TX_R0603_0OHM_H24]  8.86 15.81 270 top
R3814  100KOhm  [TX_R0402]  14.02 34.34 0 top
R3815  0Ohm  [TX_R0402_0OHM]  15.7 46.46 180 top
R3816  0Ohm  [TX_R0402_0OHM]  14.43 30.25 180 top
R3817  0Ohm  [TX_R0402_0OHM]  7.37 37.26 90 top
R3818  0Ohm  [TX_R0402_0OHM]  15.8 41 180 bottom
R3819  0Ohm  [TX_R0402_0OHM]  14.35 55.48 270 top
R3820  33Ohm  [TX_R0402]  21.82 29.18 180 bottom
R3821  0Ohm  [TX_R0402_0OHM]  12.42 23.25 90 top
R3822  10KOhm  [TX_R0402]  12.98 21.57 270 bottom
R3823  1KOhm  [TX_R0402]  14.28 22 0 bottom
R3824  100KOhm  [TX_R0402]  20.39 34.89 270 bottom
R3825  0Ohm  [TX_R0402_0OHM]  10.69 22.56 0 bottom
R3826  10KOhm  [TX_R0402]  12.24 21.64 180 top
R3827  0Ohm  [TX_R0402_0OHM]  15.55 36.84 180 top
R3828  1KOhm  [TX_R0402]  9.14 39.45 180 bottom
R3829  1KOhm  [TX_R0402]  14.3 43.28 180 bottom
R3901  0Ohm  [TX_R0402_SHORT]  37.72 65.33 90 top
R3902  0Ohm  [TX_R0402_SHORT]  35.48 57.2 90 top
R3903  0Ohm  [TX_R0402_0OHM]  34.57 57.2 270 top
R3904  0Ohm  [TX_R0402_0OHM]  39.73 59.97 0 top
R3905  0Ohm  [TX_R0402_SHORT]  34.01 65.36 90 top
R3907  33Ohm  [TX_R0402]  31.27 64.45 180 top
R3908  0Ohm  [TX_R0402_SHORT]  31.27 62.6 180 top
R3909  33Ohm  [TX_R0402]  30.99 61.67 180 top
R3910  33Ohm  [TX_R0402]  32.69 57.2 270 top
R3911  10KOhm  [TX_R0402]  33.66 57.2 270 top
R3912  0Ohm  [TX_R0402_0OHM]  31.37 57.08 0 top
R3913  10KOhm  [TX_R0402]  31.27 63.53 180 top
R3914  0Ohm  [TX_R0402_0OHM]  39.73 59.06 0 top
R3915  0Ohm  [TX_R0402_0OHM]  36.8 65.33 270 top
R3916  10KOhm  [TX_R0402]  33.02 65.36 270 top
R3917  0Ohm  [TX_R0402_0OHM]  38.98 65.76 0 top
R3918  0Ohm  [TX_R0402_0OHM]  38.98 64.85 0 top
R5000  499Ohm  [TX_R0402]  12.7 92.05 0 top
R5001  560Ohm  [TX_R0402]  12.95 92.99 0 top
R5002  100KOhm  [TX_R0402]  23.9 89.89 90 top
R5004  10KOhm  [TX_R0402]  31.47 93.32 90 top
R5100  470Ohm  [TX_R0402]  89.79 14.05 270 bottom
R5101  5.1KOhm  [TX_R0402]  171.21 19.8 270 bottom
R5102  10KOhm  [TX_R0402]  54.72 7.9 90 top
R5103  2.7KOhm  [TX_R0402]  51.74 7.9 90 top
R5104  4.7KOhm  [TX_R0402]  52.67 7.9 90 top
R5105  4.7KOhm  [TX_R0402]  57.52 7.9 90 top
R5106  4.7KOhm  [TX_R0402]  59.35 7.9 90 top
R5107  100Ohm  [TX_R0402]  42.95 6.76 90 top
R5108  100KOhm  [TX_R0402]  55.65 7.9 90 top
R5109  0Ohm  [TX_R0402_SHORT]  42.88 8.54 270 top
R5110  10KOhm  [TX_R0402]  169.89 19.43 0 bottom
R5700  0Ohm  [TX_R0402_0OHM]  20.75 78.01 180 bottom
R5701  0Ohm  [TX_R0402_0OHM]  20.75 79.02 180 bottom
R5702  1KOhm  [TX_R0402]  22.38 78.01 180 bottom
R5703  1KOhm  [TX_R0402]  22.38 79.02 180 bottom
R5704  20KOhm  [TX_R0402]  22.22 77.71 90 top
R5705  1KOhm  [TX_R0402]  22.77 76.43 180 top
R5706  0Ohm  [TX_R0402_0OHM]  25.1 77.42 270 top
R5707  1KOhm  [TX_R0402]  24.16 77.42 90 top
R5709  4.7KOhm  [TX_R0402]  22.63 84.48 90 bottom
R5710  100KOhm  [TX_R0402]  26.52 87.71 0 top
R5711  100KOhm  [TX_R0402]  24.71 87.71 0 top
R5712  0Ohm  [TX_R0402_SHORT]  16.05 77.17 90 bottom
R5714  0Ohm  [TX_R0402_SHORT]  28.88 77.37 90 top
R5716  0Ohm  [TX_R0402_0OHM]  35.08 80.11 0 top
R5717  1KOhm  [TX_R0402]  33.05 79.1 0 top
R5718  1KOhm  [TX_R0402]  33.05 80.11 0 top
R5719  0Ohm  [TX_R0402_SHORT]  27.84 87.63 90 top
R5720  0Ohm  [TX_R0402_0OHM]  35.08 79.1 0 top
R5721  0Ohm  [TX_R0402_SHORT]  22.4 81.31 180 bottom
R5722  0Ohm  [TX_R0402_SHORT]  22.39 83.16 180 bottom
R5723  0Ohm  [TX_R0402_0OHM]  22.39 82.25 180 bottom
R5724  0Ohm  [TX_R0402_0OHM]  22.4 80.39 180 bottom
R5725  100KOhm  [TX_R0402]  24.44 86.77 0 top
R5800  10KOhm  [TX_R0402]  26.29 59.13 90 top
R5801  0Ohm  [TX_R0402_SHORT]  26.29 60.78 90 top
R5802  4.7KOhm  [TX_R0402]  45.44 80.93 0 top
R5803  100KOhm  [TX_R0402]  41.68 83.11 180 top
R5804  10KOhm  [TX_R0402]  41.68 82.18 180 top
R5805  0Ohm  [TX_R0402_SHORT]  36.98 81.56 90 top
R5806  10KOhm  [TX_R0402]  38.02 81.56 90 top
R5807  4.7KOhm  [TX_R0402]  35.76 76.74 0 top
R5808  4.7KOhm  [TX_R0402]  43.15 72.49 180 top
R5809  4.7KOhm  [TX_R0402]  46.33 75.03 180 top
R5810  2.2kOHM  [TX_R0402]  38.96 81.56 270 top
R5811  2.2kOHM  [TX_R0402]  39.9 81.56 270 top
R5812  4.7KOhm  [TX_R0402]  40.06 83.12 0 top
R5813  10KOhm  [TX_R0402]  15.04 75.24 90 bottom
R5814  0Ohm  [TX_R0402_SHORT]  16.33 69.19 90 bottom
R5815  100KOhm  [TX_R0402]  17.2 71 90 bottom
R5816  0Ohm  [TX_R0402_0OHM]  41.05 71.27 180 top
R5817  2.2kOHM  [TX_R0402]  34.21 90.58 270 top
R5818  2.2kOHM  [TX_R0402]  34.79 73.56 0 top
R5819  24.9KOhm  [TX_R0402]  22.71 71.45 90 bottom
R5820  15KOhm  [TX_R0402]  22.71 73.08 90 bottom
R5821  100KOhm  [TX_R0402]  35.89 77.65 0 top
R5822  115KOhm  [TX_R0402]  35.76 74.91 180 top
R5823  16.2KOhm  [TX_R0402]  35.76 75.82 0 top
R5824  100KOhm  [TX_R0402]  113.94 16.89 270 bottom
R5825  0Ohm  [TX_R0402_0OHM]  119.13 18.3 90 bottom
R5826  100KOhm  [TX_R0402]  43.92 81.59 90 top
R5827  100KOhm  [TX_R0402]  42.98 81.59 90 top
R5900  100KOhm  [TX_R0402]  20.65 87.2 0 bottom
R5902  0Ohm  [TX_R0402_0OHM]  22.05 90.12 180 bottom
R5903  100KOhm  [TX_R0402]  22.45 88.45 90 bottom
R5904  100KOhm  [TX_R0402]  16.97 88.78 270 top
R5905  0Ohm  [TX_R0402_0OHM]  20.65 88.14 0 bottom
R5906  27KOhm  [TX_R0402]  19.84 88.78 270 top
R5907  54.9KOhm  [TX_R0402]  12.55 89.94 90 top
R6006  1KOhm  [TX_R0402]  161.52 74.15 0 bottom
R6007  1KOhm  [TX_R0402]  161.9 103.76 90 bottom
R6008  1.69KOHM  [TX_R0402]  162.84 103.76 90 bottom
R6200  8.45KOhm  [TX_R0402]  156.36 93.58 270 top
R6201  2KOhm  [TX_R0402]  148.27 91.65 270 bottom
R6202  2KOhm  [TX_R0402]  155.09 92.97 180 top
R6203  8.45KOhm  [TX_R0402]  155.09 93.91 0 top
R6204  4.75KOhm  [TX_R0402]  153.01 90.58 270 top
R6205  49.9KOhm  [TX_R0402]  151.71 90.5 0 top
R6206  4.75KOhm  [TX_R0402]  153.47 93.47 180 top
R6207  49.9KOhm  [TX_R0402]  151.71 91.44 0 top
R6300  5.1KOhm  [TX_R0402]  180.34 77.98 180 top
R6301  49.9Ohm  [TX_R0402]  180.31 81.26 180 top
R6302  10OHM  [TX_R0402]  180.34 78.92 0 top
R6303  120Ohm  [TX_R0402]  166.5 103.94 270 bottom
R6304  40.2Ohm  [TX_R0402]  169.27 105.26 0 bottom
R6305  100Ohm  [TX_R0402]  169.27 103.38 180 bottom
R6306  40.2Ohm  [TX_R0402]  167.44 103.94 270 bottom
R6307  100Ohm  [TX_R0402]  164.57 103.41 180 bottom
R6308  51.1OHM  [TX_R0402]  167.16 77.43 270 top
R6309  51.1OHM  [TX_R0402]  167.59 75.83 90 top
R6800  121OHM  [TX_R0402]  184.84 95.2 180 bottom
R6801  1KOhm  [TX_R0402]  200.43 102.14 180 bottom
R6802  1KOhm  [TX_R0402]  200.43 101.2 180 bottom
R6803  121OHM  [TX_R0402]  184.76 97.18 180 top
R6804  2.37KOHM  [TX_R0402]  147.9 77.78 90 bottom
R6805  5.49KOhm  [TX_R0402]  200.69 78.08 0 top
R6806  2.37KOHM  [TX_R0402]  184.38 96.29 0 bottom
R6807  5.49KOhm  [TX_R0402]  184.38 97.36 180 bottom
R6808  2.37KOHM  [TX_R0402]  183.21 98.81 90 top
R6809  5.49KOhm  [TX_R0402]  184.15 98.81 90 top
R6810  2.37KOHM  [TX_R0402]  200.66 77.02 0 bottom
R6811  5.49KOhm  [TX_R0402]  200.69 78.08 0 bottom
R6812  60.4Ohm  [TX_R0402]  184.25 100.89 0 bottom
R6813  60.4Ohm  [TX_R0402]  184.25 101.93 0 bottom
R6814  60.4Ohm  [TX_R0402]  200.74 80.98 180 bottom
R6815  60.4Ohm  [TX_R0402]  200.74 82.02 180 bottom
R6816  121OHM  [TX_R0402]  200.71 79.99 180 bottom
R6817  1KOhm  [TX_R0402]  200.38 76.08 180 bottom
R6818  121OHM  [TX_R0402]  200.38 75.92 180 top
R6819  1KOhm  [TX_R0402]  200.36 75.14 180 bottom
R6900  0Ohm  [TX_R0402_0OHM]  147.32 88.24 90 bottom
R6907  16.2KOhm  [TX_R0402]  159.87 73.56 180 bottom
R6908  0Ohm  [TX_R0402_0OHM]  164.64 81.99 270 top
R6910  10KOhm  [TX_R0402]  163.08 73.83 90 bottom
R6911  10KOhm  [TX_R0402]  164.02 73.83 90 bottom
R6912  4.7KOhm  [TX_R0402]  165.39 73.62 90 bottom
R6913  4.7KOhm  [TX_R0402]  166.33 73.62 90 bottom
R6914  10KOhm  [TX_R0402]  145.77 77.4 180 bottom
R6934  4.7KOhm  [TX_R0402]  160.5 81.26 315 top
R6935  4.7KOhm  [TX_R0402]  161.26 82.02 315 top
R6936  1KOhm  [TX_R0402]  168.58 79.66 270 top
R6937  4.7KOhm  [TX_R0402]  141.81 81.21 45 top
R6938  4.7KOhm  [TX_R0402]  152.32 73.61 0 top
R6939  10KOhm  [TX_R0402]  150.06 104.17 90 top
R6940  10KOhm  [TX_R0402]  149.1 104.17 90 top
R6941  100KOhm  [TX_R0402]  142.98 79.94 45 top
R6942  1MOhm  [TX_R0402]  148.25 87.07 270 bottom
R6943  5.1KOhm  [TX_R0402]  167.06 71.81 0 bottom
R7003  100KOhm  [TX_R0402]  191.36 109.98 90 bottom
R7004  0Ohm  [TX_R0402_0OHM]  192.35 109.98 270 bottom
R7005  10mohm  [TX_R0603_T02_H30]  184.81 108.23 0 bottom
R7200  100Ohm  [TX_R0402]  197.18 108.44 270 bottom
R7201  330Ohm  [TX_R0402]  196.62 109.73 180 bottom
R7202  330Ohm  [TX_R0402]  207.65 110.77 0 bottom
R7203  330Ohm  [TX_R0402]  155.85 107.34 270 bottom
R7204  100KOhm  [TX_R0402]  205.71 104.6 270 bottom
R7205  0 Ohm  [TX_R0402_0OHM]  207.73 101.28 90 bottom
RN2603  0Ohm  [TX_2R4P0402_47X55_COLAY]  16.82 64.65 270 bottom
RN2604  0Ohm  [TX_2R4P0402_47X55_COLAY]  16.79 62.51 270 bottom
RN2605  0Ohm  [TX_2R4P0402_47X55_COLAY]  16.79 60.23 270 bottom
RN2606  0Ohm  [TX_2R4P0402_47X55_COLAY]  16.82 66.93 270 bottom
RN3000  0Ohm  [TX_2R4P0402_47X55_COLAY]  53.34 98.53 90 bottom
RN5100  8.2KOhm  [TX_4R8P0402_H22_T01]  66.68 17.81 180 bottom
RN5101  8.2KOhm  [TX_4R8P0402_H22_T01]  70.14 17.81 180 bottom
RN5700  0Ohm  [TX_2R4P0402_47X55_COLAY]  14.63 83.04 180 bottom
RN5701  0Ohm  [TX_2R4P0402_47X55_COLAY]  13.51 88.27 90 top
RN5702  0Ohm  [TX_2R4P0402_47X55_COLAY]  17.83 85.47 270 top
RN5703  0Ohm  [TX_2R4P0402_47X55_COLAY]  17.37 78.72 270 top
RN5704  0Ohm  [TX_2R4P0402_47X55_COLAY]  18.29 83.34 270 top
RN5705  0Ohm  [TX_2R4P0402_47X55_COLAY]  21.79 81.46 270 top
SR3100  0Ohm  [TX_R0805_SHORT]  218.14 21.21 0 top
T0400  TPC26T_50  [NB_TPC26T_50]  127.2 65.8 90 top
T0401  TPC26T_50  [NB_TPC26T_50]  139.19 63.5 90 top
T0402  TPC26T_50  [NB_TPC26T_50]  139.14 65.15 90 top
T0403  TPC26T_50  [NB_TPC26T_50]  140.49 65.41 90 top
T0404  TPC26T_50  [NB_TPC26T_50]  131.47 62.87 180 bottom
T0405  TPC26T_50  [NB_TPC26T_50]  128.75 64.33 0 top
T0406  TPC26T_50  [NB_TPC26T_50]  126.28 64.05 0 top
T0407  TPC26T_50  [NB_TPC26T_50]  135.86 33.71 180 bottom
T0408  TPC26T_50  [NB_TPC26T_50]  131.95 61.25 180 bottom
T0409  TPC26T_50  [NB_TPC26T_50]  124 25.81 0 top
T0410  TPC26T_50  [NB_TPC26T_50]  130.33 65.67 90 bottom
T0411  TPC26T_50  [NB_TPC26T_50]  127.08 62.61 0 top
T0412  TPC26T_50  [NB_TPC26T_50]  127.47 64.54 0 top
T0900  TPC26T_50  [NB_TPC26T_50]  130.47 70.87 180 bottom
T0901  TPC26T_50  [NB_TPC26T_50]  135.28 40.85 90 bottom
T0902  TPC26T_50  [NB_TPC26T_50]  109.62 65.72 0 top
T0903  TPC26T_50  [NB_TPC26T_50]  139.17 66.63 90 top
T0904  TPC26T_50  [NB_TPC26T_50]  127.51 76.91 180 bottom
T0905  TPC26T_50  [NB_TPC26T_50]  108.1 64.95 0 top
T0906  TPC26T_50  [NB_TPC26T_50]  130.46 72.19 180 bottom
T0907  TPC26T_50  [NB_TPC26T_50]  130.46 69.57 180 bottom
T0908  TPC26T_50  [NB_TPC26T_50]  128.79 79.15 0 top
T0909  TPC26T_50  [NB_TPC26T_50]  129.52 80.78 0 top
T0910  TPC26T_50  [NB_TPC26T_50]  126.53 76.71 0 top
T0911  TPC26T_50  [NB_TPC26T_50]  125.99 79.23 0 top
T0912  TPC26T_50  [NB_TPC26T_50]  126.98 80.45 0 top
T0913  TPC26T_50  [NB_TPC26T_50]  128.41 81.77 0 top
T0914  TPC26T_50  [NB_TPC26T_50]  125.81 81.77 0 top
T0915  TPC26T_50  [NB_TPC26T_50]  126.32 77.98 0 top
T0916  TPC26T_50  [NB_TPC26T_50]  125.71 80.47 0 top
T0917  TPC26T_50  [NB_TPC26T_50]  127.11 81.74 0 top
T0918  TPC26T_50  [NB_TPC26T_50]  129.73 78.29 0 top
T0919  TPC26T_50  [NB_TPC26T_50]  130.03 79.56 0 top
T0920  TPC26T_50  [NB_TPC26T_50]  128.28 80.42 0 top
T0921  TPC26T_50  [NB_TPC26T_50]  127.52 79.18 0 top
T1000  TPC26T_50  [NB_TPC26T_50]  111.11 24.73 180 bottom
T1002  TPC26T_50  [NB_TPC26T_50]  106.38 44.99 0 top
T1003  TPC26T_50  [NB_TPC26T_50]  94.62 41.3 0 top
T1004  TPC26T_50  [NB_TPC26T_50]  94.21 36.53 180 bottom
T1005  TPC26T_50  [NB_TPC26T_50]  125.25 57.23 0 top
T1006  TPC26T_50  [NB_TPC26T_50]  124.92 58.5 0 top
T1100  TPC26T_50  [NB_TPC26T_50]  122.57 29.67 180 bottom
T1101  TPC26T_50  [NB_TPC26T_50]  107.37 27 180 bottom
T1103  TPC26T_50  [NB_TPC26T_50]  120.4 24.11 180 bottom
T1104  TPC26T_50  [NB_TPC26T_50]  118.33 28.62 180 bottom
T1105  TPC26T_50  [NB_TPC26T_50]  94.23 33.05 0 top
T1106  TPC26T_50  [NB_TPC26T_50]  108.13 31.65 0 top
T1107  TPC26T_50  [NB_TPC26T_50]  114.83 22.91 0 top
T1200  TPC26T_50  [NB_TPC26T_50]  100.58 42.12 180 bottom
T1201  TPC26T_50  [NB_TPC26T_50]  95.15 33.66 180 bottom
T1202  TPC26T_50  [NB_TPC26T_50]  128.73 76.41 180 bottom
T1203  TPC26T_50  [NB_TPC26T_50]  112.4 42.19 0 top
T1204  TPC26T_50  [NB_TPC26T_50]  93.27 30.91 0 top
T1205  TPC26T_50  [NB_TPC26T_50]  89.79 28.45 0 top
T1206  TPC26T_50  [NB_TPC26T_50]  108.18 25.83 180 bottom
T1207  TPC26T_50  [NB_TPC26T_50]  91.72 39.73 0 top
T1400  TPC26T_50  [NB_TPC26T_50]  128.63 62.16 0 top
T1401  TPC26T_50  [NB_TPC26T_50]  131.17 64.59 225 bottom
T1402  TPC26T_50  [NB_TPC26T_50]  122.99 28.37 180 bottom
T1500  TPC26T_50  [NB_TPC26T_50]  93.95 40.08 0 top
T1501  TPC26T_50  [NB_TPC26T_50]  110.34 26.7 180 bottom
T1502  TPC26T_50  [NB_TPC26T_50]  112.17 25.68 180 bottom
T1503  TPC26T_50  [NB_TPC26T_50]  114.81 30.66 180 bottom
T1504  TPC26T_50  [NB_TPC26T_50]  119.33 24.89 0 top
T1505  TPC26T_50  [NB_TPC26T_50]  116.36 29.54 0 top
T1506  TPC26T_50  [NB_TPC26T_50]  117.05 28.22 180 bottom
T1507  TPC26T_50  [NB_TPC26T_50]  101.65 31.88 180 bottom
T1508  TPC26T_50  [NB_TPC26T_50]  103.43 29.59 180 bottom
T1509  TPC26T_50  [NB_TPC26T_50]  120.17 22.76 0 top
T1510  TPC26T_50  [NB_TPC26T_50]  109.54 31.89 0 top
T1511  TPC26T_50  [NB_TPC26T_50]  107.47 30.53 0 top
T1512  TPC26T_50  [NB_TPC26T_50]  111.96 23.35 0 top
T1513  TPC26T_50  [NB_TPC26T_50]  119.66 42.46 0 top
T2300  TPC40  [TPC40T_68]  41.91 27.21 0 top
T2301  TPC40  [TPC40T_68]  24.59 43 0 top
T2302  TPC40  [TPC40T_68]  22.43 40.11 0 top
T2303  TPC40  [TPC40T_68]  45.31 28.6 0 top
T2304  TPC40  [TPC40T_68]  33.24 33.27 180 bottom
T2305  TPC40  [TPC40T_68]  42.57 28.83 0 top
T2306  TPC40  [TPC40T_68]  43.82 27.43 0 top
T2307  TPC40  [TPC40T_68]  37.21 26.42 0 top
T2308  TPC40  [TPC40T_68]  25.44 28.57 0 top
T2309  TPC40  [TPC40T_68]  91.82 42.65 180 bottom
T2310  TPC40  [TPC40T_68]  41.99 38.61 180 bottom
T3600  TPC40  [TPC40T_68]  101.52 12.78 0 top
T5700  TPC26T  [MX_TPC26T_S4_68]  22.28 83.99 0 top
T5701  TPC26T  [MX_TPC26T_S4_68]  21.29 85.78 0 top
T5801  TPC26T  [MX_TPC26T_S4_68]  34.65 82.88 90 top
T5802  TPC40  [TPC40T_68]  44.86 83.39 180 bottom
T5803  TPC40  [TPC40T_68]  43.64 73.59 180 bottom
T5804  TPC40  [TPC40T_68]  45.11 74.7 180 bottom
T5805  TPC26T  [MX_TPC26T_S4_68]  40.31 81.39 180 bottom
T6300  TPC26T  [MX_TPC26T_S4_68]  164.77 77.6 0 top
T6301  TPC26T  [MX_TPC26T_S4_68]  169.11 80.9 0 top
T6302  TPC26T_50  [NB_TPC26T_50]  168.86 92.99 0 top
T6303  TPC26T_50  [NB_TPC26T_50]  167.95 85.7 0 top
T6900  TPC26T_50  [NB_TPC26T_50]  167.01 80.57 0 top
T6901  TPC26T_50  [NB_TPC26T_50]  173.23 69.57 180 bottom
T6902  TPC26T_50  [NB_TPC26T_50]  169.77 73.36 180 bottom
T6903  TPC26T_50  [NB_TPC26T_50]  171.83 69.8 180 bottom
T6904  TPC26T_50  [NB_TPC26T_50]  169.6 74.91 180 bottom
T6905  TPC26T_50  [NB_TPC26T_50]  158.62 69.12 0 top
T6906  TPC26T_50  [NB_TPC26T_50]  149.43 76.3 0 top
T6907  TPC26T_50  [NB_TPC26T_50]  148.46 77.24 0 top
T6908  TPC26T_50  [NB_TPC26T_50]  153.82 73.03 0 top
T6909  TPC26T_50  [NB_TPC26T_50]  150.42 75.36 0 top
T6910  TPC26T_50  [NB_TPC26T_50]  151.71 74.78 0 top
T6911  TPC26T_50  [NB_TPC26T_50]  154.89 72.11 0 top
T6912  TPC26T_50  [NB_TPC26T_50]  155.91 69.78 0 top
T6913  TPC26T_50  [NB_TPC26T_50]  155.88 71.12 0 top
T6914  TPC26T_50  [NB_TPC26T_50]  155.55 74.88 180 bottom
T6915  TPC26T_50  [NB_TPC26T_50]  157.2 68.58 0 top
T6916  TPC26T_50  [NB_TPC26T_50]  155.91 68.43 0 top
T6917  TPC26T_50  [NB_TPC26T_50]  157.23 69.85 0 top
T6918  TPC26T_50  [NB_TPC26T_50]  162.97 75.21 180 bottom
T6919  TPC26T_50  [NB_TPC26T_50]  161.57 75.34 180 bottom
T6920  TPC26T_50  [NB_TPC26T_50]  169.27 68.61 180 bottom
T6921  TPC26T_50  [NB_TPC26T_50]  167.95 69.88 180 bottom
T6922  TPC26T_50  [NB_TPC26T_50]  165.43 71.68 180 bottom
T6923  TPC26T_50  [NB_TPC26T_50]  164.49 75.21 180 bottom
T6924  TPC26T_50  [NB_TPC26T_50]  149.15 85.98 180 bottom
T6925  TPC26T_50  [NB_TPC26T_50]  163.42 79.58 0 top
T6926  TPC26T_50  [NB_TPC26T_50]  164.62 79.1 0 top
T6927  TPC26T_50  [NB_TPC26T_50]  147.52 76.3 0 top
T6928  TPC26T_50  [NB_TPC26T_50]  160.43 85.35 0 top
T6929  TPC26T_50  [NB_TPC26T_50]  147.8 75.03 0 top
T6930  TPC26T_50  [NB_TPC26T_50]  170.92 68.48 180 bottom
T6931  TPC26T_50  [NB_TPC26T_50]  172.34 68.35 180 bottom
T6932  TPC26T_50  [NB_TPC26T_50]  169.39 71.1 180 bottom
T6933  TPC26T_50  [NB_TPC26T_50]  170.74 70.72 180 bottom
T6934  TPC26T_50  [NB_TPC26T_50]  170.18 72.14 180 bottom
T6935  TPC26T_50  [NB_TPC26T_50]  162.28 80.34 0 top
T6936  TPC26T_50  [NB_TPC26T_50]  169.67 69.85 180 bottom
T6937  TPC26T_50  [NB_TPC26T_50]  146.46 75.59 0 top
T6938  TPC26T_50  [NB_TPC26T_50]  144.78 79.73 0 top
T6939  TPC26T_50  [NB_TPC26T_50]  167.87 68.43 180 bottom
T6940  TPC26T_50  [NB_TPC26T_50]  150.11 92.38 0 top
T6941  TPC26T_50  [NB_TPC26T_50]  162.15 82.48 0 top
T6943  TPC26T_50  [NB_TPC26T_50]  177.8 71.33 0 top
T6944  TPC26T_50  [NB_TPC26T_50]  163.5 82.02 0 top
T6945  TPC26T_50  [NB_TPC26T_50]  177.57 69.83 0 top
T6946  TPC26T_50  [NB_TPC26T_50]  177.57 67.92 0 top
T6947  TPC26T_50  [NB_TPC26T_50]  149.86 84.64 180 bottom
T6948  TPC26T_50  [NB_TPC26T_50]  160.27 75.82 180 bottom
TR3700  100KOHM  [TX_R0402_H24]  105.77 46.33 0 top
U0400  942318  [BGA_1356P_1654X945_INTEL]  115.98 53.02 270 bottom
U0500  SN74AUP1G07DCKR  [TX_SC70_S5_TI]  94.51 110.67 180 bottom
U1200  TC7SZ08FU  [TX_SC70_S5_TI]  98.37 27.78 180 bottom
U1201  TC7SZ08FU  [TX_SC70_S5_TI]  74.22 17.88 180 bottom
U1202  TC7SZ08FU  [TX_SC70_S5_TI]  74.24 15.32 180 bottom
U1203  TC7SZ08FU  [TX_SC70_S5_TI]  100.23 25.05 0 bottom
U1204  SN74AUP1G07DCKR  [TX_SC70_S5_TI]  96.98 14.46 180 bottom
U1800  TC7SZ08FU  [TX_SC70_S5_TI]  78.23 19.31 0 bottom
U1900  W25Q128JVSIQ  [TX_SOIC_8P_50_213X213]  99.31 20.78 90 bottom
U2300  MEC1416-NU-D0  [TX_QFP_128P_16_559X559]  34.7 36.1 180 top
U2500  H26M88002AMR  [A_BGA_153P_20_516X457_H39]  100.78 22.03 270 top
U2600  PUSB3F96  [TX_DFN_10P_20_102X43_COLAY]  14.25 66.07 270 bottom
U2601  PUSB3F96  [TX_DFN_10P_20_102X43_COLAY]  14.17 61.24 90 bottom
U3000  G5244T11U  [TX_SOT23_S5_H57]  47.47 99.57 0 bottom
U3100  G524C1T11U  [TX_SOT23_S5_2D4_H57]  106.12 12.51 270 bottom
U3700  NCT7718W  [TX_SOIC_8P_26_122X122]  130.56 90.21 90 bottom
U3701  LNG2DMTR  [TX_LGA_12P_20_87X87_ST]  153.9 21.49 270 top
U3702  BU52061NVX-TR  [TX_DFN_4P_26_51X67_P_1V]  1.63 54.55 180 top
U3800  ALC3254-CG  [TX_QFN_48P_16_S240_P_9V_REA]  17.04 29.24 270 bottom
U3901  NPCT650VBCYX  [A_QFN_32P_20_S197_PAD_T01]  35.48 61.32 90 top
U5100  RN4904 2-2J1A  [TX_SOT363_PHILIPS]  84.43 17.55 90 bottom
U5101  G517E2T11U  [TX_SOT23_S5_2D4_122X67_H57]  202.92 45.85 180 bottom
U5700  PUSB3F96  [TX_DFN_10P_20_102X43_COLAY]  12.43 84.31 270 top
U5701  PUSB3F96  [TX_DFN_10P_20_102X43_COLAY]  12.59 80.77 90 top
U5702  TS3DS10224RUKR  [A_QFN_20P_16_122X122_P_5V]  17.68 80.39 0 bottom
U5703  TUSB546-DCIRNQR  [TX_QFN_40P_16_161X240_PD_8V]  26.71 82.7 0 top
U5800  CYPD4125-40LQXIT  [TX_QFN_40P_20_S240_P_4V]  40.41 76.74 90 top
U5801  G517B1T11U  [TX_SOT23_S5_2D4_T02X01_H57]  40.85 19.76 270 bottom
U5802  AP2204K-ADJTRG1  [TX_SOT23_S5_2D4_T02X01_H57]  19.94 71.86 90 bottom
U5900  DPS1113FIA-13-F  [A_QFN_17P_20_S161_P_8V]  17.68 91.19 270 bottom
U6000  R17M-M2-50  [TX_BGA_631P_909X909_AMD]  162.83 88.82 90 bottom
U6001  TC7SZ08FU  [TX_SC70_S5_TI]  137.67 87.58 180 bottom
U6800  K4G80325FB-HC03  [TX_BGA_170P_31_555X476]  192.56 98.58 270 bottom
U6801  K4G80325FB-HC03  [TX_BGA_170P_31_555X476]  192.56 98.58 90 top
U6802  K4G80325FB-HC03  [TX_BGA_170P_31_555X476]  192.57 79.6 90 bottom
U6803  K4G80325FB-HC03  [TX_BGA_170P_31_555X476]  192.57 79.6 270 top
U6903  TC7SZ08FU  [TX_SC70_S5_TI]  141.75 88.02 90 bottom
U7000  G5016KD1U  [TX_DFN_10P_16_122X83_PAD]  188.24 109.96 270 bottom
X0900  24MHZ  [TX_XTAL_4P_126X98_HELE]  129.27 24.6 180 bottom
X1000  24MHZ  [TX_XTAL_4P_126X98_HELE]  134.6 53.58 90 bottom
X1001  32.768KHZ  [TX_XTAL_2P_126X59]  90.91 42.17 270 top
X2300  32.768KHZ  [TX_XTAL_2P_126X59]  45.93 45.46 0 top
X6900  27MHZ  [TX_XTAL_4P_126X98_HELE_H35]  144.83 87.73 270 bottom

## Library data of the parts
